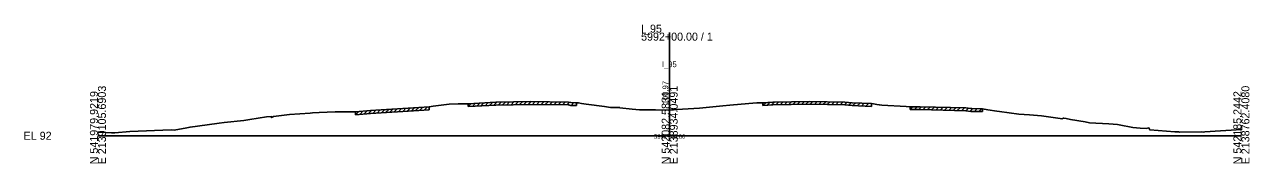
# Model space of a CAD drawing. Extents: x -12534 to 3403, y -1332 to 21983.
# Drawn here: x -25.7 to 402.8, y 19490.3 to 19538.9 of the extents above; entities that cross this region are included whole.
import ezdxf

# ---------------------------------------------------------------- set-up
doc = ezdxf.new("R2010")
doc.units = 0
for name, color, linetype in [('RD_GPK_XS_Cell', 7, 'Continuous'), ('RD_XS_ExGround', 7, 'Continuous'), ('RD_XS_ExPaveRet', 7, 'Continuous'), ('RD_XS_TX_Baseline', 7, 'Continuous'), ('RD_XS_TX_Elev_EX', 7, 'Continuous'), ('RD_XS_TX_Station', 7, 'Continuous')]:
    doc.layers.add(name, color=color, linetype=linetype)

msp = doc.modelspace()

# ---------------------------------------------------------------- linework, layer by layer
at = {"layer": 'RD_GPK_XS_Cell'}
for p, q in [((200, 19500), (200, 19536.03)), ((0, 19500), (200, 19500)), ((200, 19500), (400, 19500))]:
    msp.add_line(p, q, dxfattribs=at)
at = {"layer": 'RD_XS_ExGround'}
msp.add_lwpolyline([(0, 19501.29), (0.79, 19501.29), (4.77, 19501.03), (5.94, 19500.99), (11.16, 19501.43), (25.66, 19502.05), (26.72, 19501.96), (31.08, 19502.73), (32.25, 19503.03), (41.58, 19504.3), (42.38, 19504.41), (44.14, 19504.61), (50.98, 19505.38), (53.14, 19505.69), (58.95, 19506.59), (60.6, 19506.72), (60.76, 19506.34), (61.39, 19506.7), (66.98, 19507.4), (74.25, 19507.94), (75.01, 19507.99), (77.4, 19508.09), (83, 19508.36), (84.82, 19508.37), (90.14, 19508.36), (95.33, 19508.78), (112.29, 19509.87), (115.91, 19510.06), (117.26, 19510.3), (122.88, 19511.03), (126.07, 19511.2), (129.5, 19511.19), (139.2, 19511.71), (151.44, 19511.95), (164.57, 19511.75), (165.43, 19511.6), (167.04, 19511.54), (167.42, 19511.55), (168.07, 19511.46), (169.17, 19511.31), (170.82, 19511.08), (177.18, 19510.19), (179.26, 19509.92), (182.47, 19509.89), (182.54, 19509.77), (186.87, 19509.32), (189.44, 19509.06), (195.09, 19509.1), (200.06, 19508.96), (200.73, 19509.03), (201.39, 19509.07), (202.49, 19509.16), (210.43, 19509.64), (218.62, 19510.42), (221.1, 19510.69), (227.65, 19511.22), (230.51, 19511.46), (231.85, 19511.55), (232.63, 19511.55), (236.12, 19511.78), (248.99, 19512.01), (261.3, 19511.75), (263.89, 19511.54), (270.62, 19511.22), (271.34, 19511.12), (272.46, 19510.95), (273.39, 19510.79), (274.25, 19510.73), (282.69, 19510.2), (284.12, 19510.15), (287.62, 19510.12), (303.58, 19509.72), (305.32, 19509.53), (305.71, 19509.52), (309.41, 19509.44), (311.25, 19509.11), (314.41, 19508.61), (315.42, 19508.45), (322.19, 19507.59), (325.9, 19507.27), (330.07, 19506.91), (336.59, 19506.01), (337.15, 19505.95), (337.82, 19506.2), (338.72, 19505.99), (340.17, 19505.71), (345.4, 19504.82), (346.9, 19504.56), (353.59, 19504.11), (356.63, 19503.91), (357.2, 19503.82), (362.05, 19502.9), (364.57, 19502.61), (366.73, 19502.55), (367.68, 19502.73), (367.95, 19502.11), (376.72, 19501.41), (377.96, 19501.32), (378.34, 19501.3), (386.2, 19501.31), (386.61, 19501.3), (387.19, 19501.31), (400, 19502.17)], dxfattribs=at)
at = {"layer": 'RD_XS_ExPaveRet'}
for p, q in [((129.5, 19510.19), (130.55, 19511.25)), ((129.5, 19510.19), (129.5, 19511.19)), ((131, 19510.27), (132.05, 19511.33)), ((132.5, 19510.35), (133.55, 19511.41)), ((134, 19510.43), (135.05, 19511.49)), ((135.5, 19510.51), (136.55, 19511.57)), ((137, 19510.59), (138.05, 19511.65)), ((138.5, 19510.67), (139.54, 19511.71)), ((140, 19510.72), (141.02, 19511.74)), ((141.5, 19510.75), (142.52, 19511.77)), ((143, 19510.78), (144.02, 19511.8)), ((144.5, 19510.81), (145.52, 19511.83)), ((146, 19510.84), (147.02, 19511.86)), ((147.5, 19510.87), (148.52, 19511.9)), ((149, 19510.9), (150.02, 19511.93)), ((150.5, 19510.94), (151.51, 19511.95)), ((152, 19510.95), (152.98, 19511.93)), ((153.5, 19510.92), (154.48, 19511.91)), ((155, 19510.9), (155.98, 19511.88)), ((156.5, 19510.87), (157.48, 19511.86)), ((158, 19510.85), (158.98, 19511.83)), ((159.5, 19510.83), (160.48, 19511.81)), ((161, 19510.8), (161.98, 19511.79)), ((162.5, 19510.78), (163.48, 19511.76)), ((164, 19510.75), (164.93, 19511.69)), ((165.5, 19510.6), (166.46, 19511.56)), ((167.42, 19511.55), (167.42, 19510.55)), ((232.63, 19510.55), (233.71, 19511.62)), ((232.63, 19510.55), (232.63, 19511.55)), ((234.13, 19510.65), (235.21, 19511.72)), ((235.63, 19510.75), (236.68, 19511.79)), ((237.13, 19510.8), (238.15, 19511.82)), ((238.63, 19510.83), (239.65, 19511.84)), ((240.13, 19510.85), (241.15, 19511.87)), ((241.63, 19510.88), (242.65, 19511.9)), ((243.13, 19510.91), (244.15, 19511.92)), ((244.63, 19510.93), (245.65, 19511.95)), ((246.13, 19510.96), (247.15, 19511.98)), ((247.63, 19510.99), (248.65, 19512)), ((249.13, 19511.01), (250.11, 19511.99)), ((250.63, 19510.97), (251.61, 19511.95)), ((252.13, 19510.94), (253.11, 19511.92)), ((253.63, 19510.91), (254.61, 19511.89)), ((255.13, 19510.88), (256.11, 19511.86)), ((256.63, 19510.85), (257.61, 19511.83)), ((258.13, 19510.82), (259.11, 19511.8)), ((259.63, 19510.78), (260.61, 19511.76)), ((261.13, 19510.75), (262.07, 19511.69)), ((262.63, 19510.64), (263.56, 19511.57)), ((264.13, 19510.53), (265.09, 19511.49)), ((265.63, 19510.46), (266.59, 19511.42)), ((267.13, 19510.39), (268.09, 19511.34)), ((268.63, 19510.32), (269.59, 19511.27)), ((270.62, 19511.22), (270.62, 19510.22)), ((90.14, 19507.36), (91.22, 19508.45)), ((90.14, 19507.36), (90.14, 19508.36)), ((90.14, 19507.36), (95.33, 19507.78)), ((91.64, 19507.48), (92.72, 19508.57)), ((93.14, 19507.6), (94.22, 19508.69)), ((94.64, 19507.72), (95.72, 19508.8)), ((95.33, 19507.78), (112.29, 19508.87)), ((96.14, 19507.83), (97.21, 19508.9)), ((97.64, 19507.93), (98.71, 19509)), ((99.14, 19508.02), (100.21, 19509.09)), ((100.64, 19508.12), (101.71, 19509.19)), ((102.14, 19508.22), (103.21, 19509.29)), ((103.64, 19508.31), (104.71, 19509.38)), ((105.14, 19508.41), (106.21, 19509.48)), ((106.64, 19508.51), (107.71, 19509.58)), ((108.14, 19508.6), (109.21, 19509.67)), ((109.64, 19508.7), (110.71, 19509.77)), ((111.14, 19508.8), (112.21, 19509.87)), ((112.29, 19508.87), (115.91, 19509.06)), ((112.64, 19508.89), (113.69, 19509.94)), ((114.14, 19508.97), (115.19, 19510.02)), ((115.91, 19510.06), (115.91, 19509.06)), ((129.5, 19510.19), (139.2, 19510.71)), ((139.2, 19510.71), (151.44, 19510.95)), ((151.44, 19510.95), (164.57, 19510.75)), ((164.57, 19510.75), (165.43, 19510.6)), ((165.43, 19510.6), (167.04, 19510.54)), ((167.04, 19510.54), (167.42, 19510.55)), ((232.63, 19510.55), (236.12, 19510.78)), ((236.12, 19510.78), (248.99, 19511.01)), ((248.99, 19511.01), (261.3, 19510.75)), ((261.3, 19510.75), (263.89, 19510.54)), ((263.89, 19510.54), (270.62, 19510.22)), ((284.12, 19509.15), (284.12, 19510.15)), ((284.12, 19509.15), (285.11, 19510.14)), ((284.12, 19509.15), (287.62, 19509.12)), ((285.62, 19509.14), (286.61, 19510.13)), ((287.12, 19509.12), (288.1, 19510.11)), ((287.62, 19509.12), (303.58, 19508.72)), ((288.62, 19509.09), (289.59, 19510.07)), ((290.12, 19509.06), (291.09, 19510.03)), ((291.62, 19509.02), (292.59, 19509.99)), ((293.12, 19508.98), (294.09, 19509.96)), ((294.62, 19508.94), (295.59, 19509.92)), ((296.12, 19508.91), (297.09, 19509.88)), ((297.62, 19508.87), (298.59, 19509.85)), ((299.12, 19508.83), (300.09, 19509.81)), ((300.62, 19508.8), (301.59, 19509.77)), ((302.12, 19508.76), (303.09, 19509.73)), ((303.58, 19508.72), (305.32, 19508.53)), ((303.62, 19508.72), (304.52, 19509.62)), ((305.12, 19508.56), (306.08, 19509.51)), ((305.32, 19508.53), (305.71, 19508.52)), ((305.71, 19508.52), (309.41, 19508.44)), ((306.62, 19508.5), (307.6, 19509.48)), ((308.12, 19508.47), (309.1, 19509.45)), ((309.41, 19509.44), (309.41, 19508.44))]:
    msp.add_line(p, q, dxfattribs=at)

# ---------------------------------------------------------------- texts
at = {"layer": 'RD_GPK_XS_Cell'}
for s, p in [('I_95', (190, 19536.03)), ('5992+00.00 / 1', (190, 19533.23)), ('EL 92', (-26, 19498.6))]:
    msp.add_text(s, height=2.8, dxfattribs=at).set_placement(p)
for s, p in [('N 541979.9219', (0, 19490)), ('E 2139105.6903', (2.8, 19490)), ('N 542082.5831', (200, 19490)), ('E 2138934.0491', (202.8, 19490)), ('N 542185.2442', (400, 19490)), ('E 2138762.4080', (402.8, 19490))]:
    msp.add_text(s, height=2.8, rotation=90, dxfattribs=at).set_placement(p)
at = {"layer": 'RD_XS_TX_Baseline'}
msp.add_text('I_95', height=2, dxfattribs=at).set_placement((197.28, 19523.97))
at = {"layer": 'RD_XS_TX_Elev_EX'}
msp.add_text('100.97', height=2, rotation=90, dxfattribs=at).set_placement((199.5, 19510.97))
at = {"layer": 'RD_XS_TX_Station'}
msp.add_text('5992+00.00', height=1.5, dxfattribs=at).set_placement((194.51, 19498.97))

doc.saveas('drawing.dxf')
